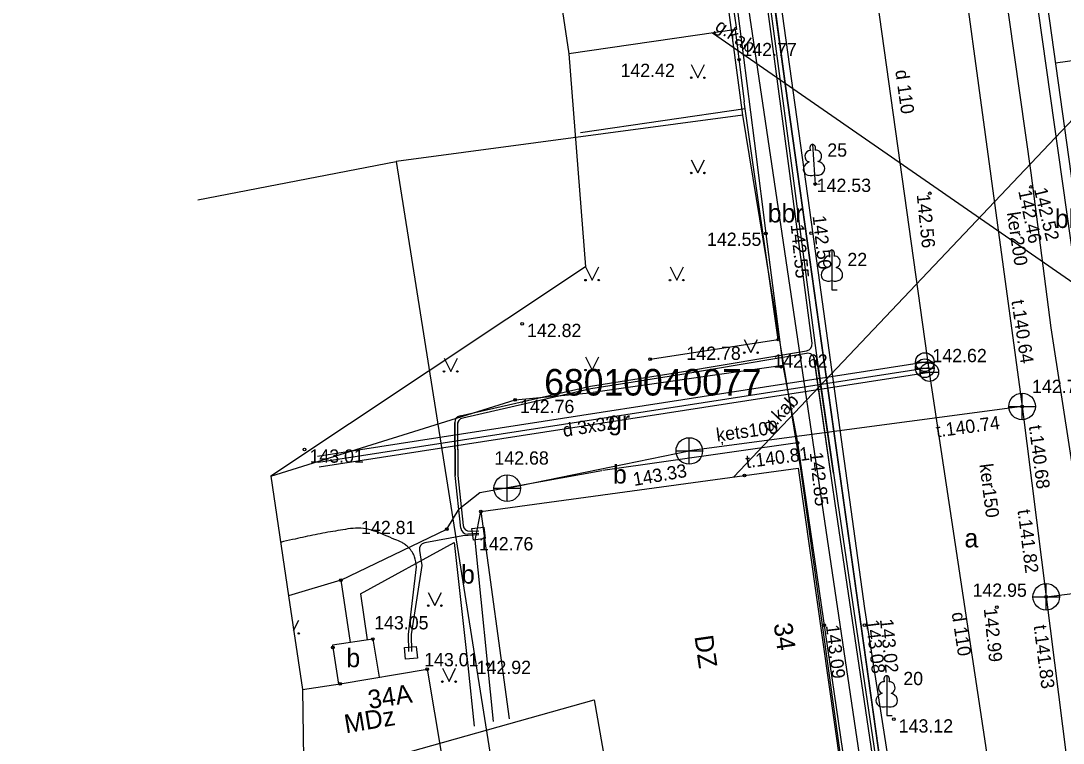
# Model space of a CAD drawing. Extents: x 728710 to 728960, y 272811 to 273475.
# Drawn here: x 728796 to 728835.24, y 273006.07 to 273033.26 of the extents above; entities that cross this region are included whole.
import ezdxf

# ---------------------------------------------------------------- set-up
doc = ezdxf.new("R2010")
doc.units = 0
for name, color, linetype in [('GEOD_ELEM_####_TKST_#', 7, 'Continuous'), ('Level 15', 7, 'Continuous'), ('Level 17', 7, 'Continuous'), ('Level 23', 7, 'Continuous'), ('Level 27', 7, 'Continuous'), ('Level 29', 7, 'Continuous'), ('Level 3', 7, 'Continuous'), ('Level 36', 7, 'Continuous'), ('Level 39', 7, 'Continuous'), ('Level 4', 7, 'Continuous'), ('Level 48', 7, 'Continuous'), ('Level 50', 7, 'Continuous'), ('Level 55', 7, 'Continuous'), ('Level 56', 7, 'Continuous'), ('Level 57', 7, 'Continuous'), ('Level 58', 7, 'Continuous'), ('Level 59', 7, 'Continuous'), ('Level 60', 7, 'Continuous'), ('Level 62', 7, 'Continuous'), ('Level 9', 7, 'Continuous'), ('PNTNO', 7, 'Continuous'), ('RAMI_UZMR_####_####_#', 7, 'Continuous'), ('RELJ_ELEM_####_####_#', 7, 'Continuous'), ('RELJ_NOGA_####_####_#', 7, 'Continuous'), ('ROBZ_ELEM_####_####_#', 7, 'Continuous'), ('ROBZ_KADS_####_TKST_#', 7, 'Continuous'), ('ROBZ_UZMR_####_####_#', 7, 'Continuous'), ('SAKT_VADV_PKAB_TKST_#', 7, 'Continuous'), ('TERT_ELEM_####_####_#', 7, 'Continuous'), ('TERT_KONT_####_####_#', 7, 'Continuous')]:
    doc.layers.add(name, color=color, linetype=linetype)

msp = doc.modelspace()

# ---------------------------------------------------------------- linework, layer by layer
at = {"layer": 'GEOD_ELEM_####_TKST_#'}
msp.add_lwpolyline([(728828.856, 273003.445), (728828.68, 273003.642), (728828.556, 273003.935), (728824.783, 273030.792), (728823.249, 273042.16), (728821.524, 273054.142), (728821.778, 273054.372)], dxfattribs=at)
at = {"layer": 'Level 15'}
for points in [[(728813.484, 273013.771), (728813.04, 273013.714), (728812.984, 273014.151), (728813.428, 273014.208)], [(728810.93, 273009.276), (728810.485, 273009.232), (728810.442, 273009.67), (728810.887, 273009.714)]]:
    msp.add_lwpolyline(points, close=True, dxfattribs=at)
at = {"layer": 'Level 17'}
for p, q in [((728807.174, 273016.87), (728830.144, 273020.432)), ((728807.209, 273016.644), (728830.179, 273020.207)), ((728807.236, 273016.472), (728830.206, 273020.034))]:
    msp.add_line(p, q, dxfattribs=at)
for points in [[(728826.802, 273044.347), (728830.203, 273020.034)], [(728830.203, 273020.034), (728832.551, 273004.399)]]:
    msp.add_lwpolyline(points, dxfattribs=at)
at = {"layer": 'Level 23'}
msp.add_line((728814.314, 273015.667), (728821.168, 273017.069), dxfattribs=at)
for points in [[(728826.189, 273073.896), (728833.694, 273018.747), (728821.168, 273017.069)], [(728833.694, 273018.747), (728834.604, 273011.578), (728842.609, 273012.599)], [(728834.604, 273011.578), (728838.604, 272979.894), (728842.796, 272980.305)]]:
    msp.add_lwpolyline(points, dxfattribs=at)
at = {"layer": 'Level 27'}
for points in [[(728822.896, 273032.936), (728823.238, 273030.207)], [(728819.695, 273020.523), (728824.516, 273021.259), (728823.238, 273030.207)], [(728823.275, 273029.949), (728817.067, 273029.042)]]:
    msp.add_lwpolyline(points, dxfattribs=at)
at = {"layer": 'Level 29'}
for p, q in [((728833.694, 273018.247), (728833.694, 273019.247)), ((728833.194, 273018.747), (728834.194, 273018.747)), ((728821.168, 273016.569), (728821.168, 273017.569)), ((728820.668, 273017.069), (728821.668, 273017.069)), ((728814.314, 273015.167), (728814.314, 273016.167)), ((728813.814, 273015.667), (728814.814, 273015.667)), ((728834.604, 273011.078), (728834.604, 273012.078)), ((728834.104, 273011.578), (728835.104, 273011.578))]:
    msp.add_line(p, q, dxfattribs=at)
for centre in [(728833.694, 273018.747), (728821.168, 273017.069), (728814.314, 273015.667), (728834.604, 273011.578)]:
    msp.add_circle(centre, 0.5, dxfattribs=at)
at = {"layer": 'Level 3'}
for p, q in [((728821.012, 273046.132), (728822.94, 273032.932)), ((728822.94, 273032.932), (728816.634, 273032.011)), ((728813.325, 273014.791), (728825.26, 273016.422)), ((728825.26, 273016.422), (728827.025, 273004.043)), ((728813.325, 273014.791), (728814.392, 273006.984)), ((728808.027, 273008.309), (728811.305, 273008.858)), ((728806.601, 273008.097), (728808.027, 273008.309))]:
    msp.add_line(p, q, dxfattribs=at)
msp.add_lwpolyline([(728811.305, 273008.858), (728812.119, 273004.001), (728808.786, 273003.415)], dxfattribs=at)
at = {"layer": 'Level 36'}
for p, q in [((728826.493, 273016.224), (728825.862, 273020.594)), ((728812.442, 273018.145), (728812.457, 273016.145))]:
    msp.add_line(p, q, dxfattribs=at)
for points in [[(728826.592, 273016.238), (728825.961, 273020.608)], [(728812.342, 273018.144), (728812.357, 273016.144)]]:
    msp.add_lwpolyline(points, dxfattribs=at)
at = {"layer": 'Level 39'}
for p, q in [((728829.682, 273020.414), (728830.384, 273020.414)), ((728830.032, 273020.414), (728830.032, 273020.415)), ((728829.681, 273020.184), (728830.383, 273020.184)), ((728829.852, 273020.034), (728830.554, 273020.034)), ((728830.031, 273020.184), (728830.031, 273020.185)), ((728830.202, 273020.034), (728830.202, 273020.035))]:
    msp.add_line(p, q, dxfattribs=at)
for centre in [(728830.033, 273020.414), (728830.032, 273020.184), (728830.203, 273020.034)]:
    msp.add_circle(centre, 0.351, dxfattribs=at)
at = {"layer": 'Level 4'}
for p, q in [((728820.196, 273055.436), (728823.604, 273028.739)), ((728834.947, 273031.673), (728843.115, 273032.795)), ((728823.604, 273028.739), (728824.1, 273024.852)), ((728824.1, 273024.852), (728824.683, 273020.291)), ((728824.683, 273020.291), (728817.545, 273019.273)), ((728825.242, 273017.378), (728817.914, 273016.333)), ((728825.242, 273017.378), (728827.666, 273000.729))]:
    msp.add_line(p, q, dxfattribs=at)
for points in [[(728845.654, 273100.85), (728832.719, 273098.413), (728826.071, 273097.316), (728825.017, 273097.001), (728824.765, 273096.832), (728824.532, 273096.455), (728824.532, 273096.455), (728826.161, 273084.877), (728827.437, 273076.575), (728829.749, 273059.3), (728831.728, 273043.761), (728834.021, 273027.538), (728834.782, 273021.709), (728836.279, 273011.943), (728839.357, 272993.501), (728839.499, 272992.383), (728841.21, 272978.381), (728843.301, 272966.86), (728843.797, 272965.94)], [(728845.919, 273099.374), (728832.98, 273096.936), (728826.409, 273095.852), (728826.143, 273095.772), (728827.647, 273085.083), (728828.941, 273076.709), (728831.314, 273059.418), (728833.202, 273044.226), (728835.526, 273027.512), (728836.266, 273021.924), (728837.76, 273012.18), (728840.331, 272994.327), (728840.331, 272994.327), (728840.331, 272994.327), (728842.687, 272979.229), (728844.615, 272968.066)], [(728791.727, 273091.506), (728811.654, 273095.023), (728814.654, 273095.178), (728815.22, 273095.032), (728815.785, 273094.657), (728816.384, 273093.154), (728816.384, 273093.154), (728817.477, 273084.163), (728819.263, 273073.354), (728821.261, 273057.957), (728825.757, 273025.679), (728827.763, 273011.141), (728832.943, 272977.993), (728834.913, 272963.328)], [(728824.683, 273020.291), (728825.242, 273017.378)], [(728814.609, 273018.994), (728817.545, 273019.273)], [(728805.412, 273016.121), (728814.609, 273018.994)], [(728812.039, 273014.124), (728812.509, 273014.896), (728813.281, 273015.51), (728817.878, 273016.34)], [(728813.801, 273006.889), (728813.108, 273013.716), (728813.325, 273014.791)], [(728808.054, 273012.208), (728812.039, 273014.124)], [(728808.788, 273011.694), (728812.319, 273013.625), (728812.828, 273008.991), (728813.069, 273006.707)], [(728808.054, 273012.208), (728806.079, 273011.62)], [(728808.054, 273012.208), (728808.402, 273009.866)], [(728808.788, 273011.694), (728809.045, 273009.961)]]:
    msp.add_lwpolyline(points, dxfattribs=at)
at = {"layer": 'Level 48'}
for centre in [(728823.039, 273031.795), (728825.9, 273027.115), (728834.029, 273027.004), (728830.224, 273026.767), (728824.049, 273025.255), (728825.757, 273025.265), (728814.874, 273021.856), (728824.516, 273021.259), (728819.695, 273020.523), (728819.695, 273020.523), (728824.621, 273020.24), (728814.609, 273018.994), (728833.694, 273018.747), (728806.685, 273017.128), (728825.242, 273017.378), (728823.242, 273016.15), (728813.325, 273014.791), (728812.039, 273014.124), (728808.054, 273012.208), (728834.605, 273011.581), (728832.748, 273011.189), (728826.248, 273010.515), (728827.763, 273010.515), (728807.752, 273009.677), (728809.258, 273009.993), (728811.305, 273008.858), (728813.582, 273009.049), (728808.027, 273008.309), (728828.868, 273006.976)]:
    msp.add_circle(centre, 0.05, dxfattribs=at)
at = {"layer": 'Level 9'}
for p, q in [((728809.258, 273009.993), (728807.739, 273009.767)), ((728807.739, 273009.767), (728807.957, 273008.299)), ((728809.258, 273009.993), (728809.499, 273008.555))]:
    msp.add_line(p, q, dxfattribs=at)
at = {"layer": 'RAMI_UZMR_####_####_#'}
for points in [[(728810.894, 273070.336), (728816.634, 273032.011), (728817.26, 273023.998), (728805.412, 273016.121), (728806.079, 273011.62), (728806.601, 273008.097), (728806.659, 273004.632), (728817.58, 273007.699), (728824.279, 272969.525), (728810.963, 272966.628), (728810.935, 272966.213), (728811.098, 272962.191), (728811.981, 272950.771), (728813.612, 272944.45), (728830.483, 272947.485), (728837.542, 272895.947)], [(728842.48, 273036.82), (728822.849, 273016.092)], [(728822.045, 273032.801), (728845.408, 273016.627)]]:
    msp.add_lwpolyline(points, dxfattribs=at)
at = {"layer": 'RELJ_ELEM_####_####_#'}
msp.add_lwpolyline([(728821.778, 273054.372), (728821.586, 273054.209), (728821.524, 273054.142), (728821.54, 273054.018), (728823.24, 273042.315), (728824.783, 273030.792), (728828.544, 273004.011), (728828.618, 273003.789), (728828.856, 273003.445)], dxfattribs=at)
at = {"layer": 'ROBZ_ELEM_####_####_#'}
msp.add_lwpolyline([(728815.186, 273091.969), (728820.435, 273053.684), (728833.431, 272966.054)], dxfattribs=at)
at = {"layer": 'ROBZ_UZMR_####_####_#'}
for p, q in [((728823.179, 273029.707), (728820.023, 273053.364)), ((728823.179, 273029.707), (728810.138, 273027.96)), ((728825.364, 273016.401), (728823.179, 273029.707)), ((728802.665, 273026.519), (728810.138, 273027.96)), ((728810.138, 273027.96), (728814.417, 273000.979)), ((728827.101, 273003.875), (728825.364, 273016.401))]:
    msp.add_line(p, q, dxfattribs=at)
at = {"layer": 'TERT_ELEM_####_####_#'}
for p, q in [((728812.919, 273014.046), (728813.24, 273014.067)), ((728812.645, 273013.878), (728811.208, 273013.612)), ((728813.25, 273013.918), (728812.645, 273013.878)), ((728813.247, 273013.967), (728812.83, 273013.94)), ((728811.007, 273013.327), (728811.098, 273012.758))]:
    msp.add_line(p, q, dxfattribs=at)
for points in [[(728815.267, 273094.223), (728815.717, 273091.871), (728816.832, 273085.52), (728817.881, 273078.643), (728818.508, 273074.355), (728819.658, 273066.192), (728820.712, 273058.74), (728821.479, 273053.332), (728822.695, 273044.505), (728823.883, 273036.26), (728825.025, 273027.716), (728825.927, 273020.849), (728826.755, 273015.106), (728828.259, 273004.946), (728828.26, 273004.941)], [(728825.79, 273021.122), (728824.925, 273027.702), (728823.783, 273036.246), (728822.595, 273044.491), (728821.414, 273053.07)], [(728832.465, 273047.568), (728833.163, 273041.758), (728834, 273035.77), (728836.422, 273018.61), (728837.731, 273009.628), (728838.803, 273002.448), (728839.303, 272998.864)], [(728812.537, 273018.39), (728817.448, 273019.51), (728820.868, 273020.046), (728825.584, 273020.843)], [(728825.582, 273020.742), (728820.884, 273019.948), (728817.466, 273019.412), (728812.637, 273018.31)], [(728828.161, 273004.927), (728828.161, 273004.932), (728826.657, 273015.092), (728825.871, 273020.531)], [(728812.565, 273014.164), (728812.357, 273016.144), (728812.342, 273018.144)], [(728812.443, 273018.064), (728812.457, 273016.15), (728812.654, 273014.27)], [(728810.615, 273009.523), (728810.594, 273010.167), (728810.897, 273012.707)], [(728811.098, 273012.758), (728810.694, 273010.163), (728810.714, 273009.526)]]:
    msp.add_lwpolyline(points, dxfattribs=at)
for centre, start, end in [((728825.542, 273021.09), 279.5905, 7.4831), ((728825.624, 273020.495), 8.2139, 99.5905), ((728812.592, 273018.146), 102.8541, 180.4248), ((728812.693, 273018.066), 102.8541, 180.4248), ((728812.813, 273014.19), 185.988, 273.7394), ((728812.903, 273014.296), 185.988, 273.7394), ((728811.254, 273013.367), 100.4731, 189.1179)]:
    msp.add_arc(centre, 0.25, start, end, dxfattribs=at)
msp.add_spline([(728810.897, 273012.707), (728810.824, 273013.086), (728810.599, 273013.435), (728810.481, 273013.542), (728810.357, 273013.622), (728810.086, 273013.741), (728809.693, 273013.905), (728809.3, 273014.055), (728808.906, 273014.151), (728808.508, 273014.157), (728808.129, 273014.103), (728807.75, 273014.041), (728806.99, 273013.898), (728806.232, 273013.735), (728805.781, 273013.63)], degree=3, dxfattribs=at)
at = {"layer": 'TERT_KONT_####_####_#'}
for p, q in [((728821.24, 273031.616), (728821.49, 273031.116)), ((728821.49, 273031.116), (728821.74, 273031.616)), ((728821.24, 273028.031), (728821.49, 273027.531)), ((728821.49, 273027.531), (728821.74, 273028.031)), ((728825.878, 273027.461), (728825.9, 273027.115)), ((728825.9, 273027.115), (728826.099, 273027.128)), ((728817.26, 273023.998), (728817.51, 273023.498)), ((728817.51, 273023.498), (728817.76, 273023.998)), ((728820.444, 273023.998), (728820.694, 273023.498)), ((728820.694, 273023.498), (728820.944, 273023.998)), ((728826.534, 273023.48), (728826.534, 273023.133)), ((728826.534, 273023.133), (728826.734, 273023.133)), ((728823.237, 273021.269), (728823.487, 273020.769)), ((728823.487, 273020.769), (728823.737, 273021.269)), ((728811.936, 273020.562), (728812.186, 273020.062)), ((728812.186, 273020.062), (728812.436, 273020.562)), ((728817.26, 273020.612), (728817.51, 273020.112)), ((728817.51, 273020.112), (728817.76, 273020.612)), ((728811.339, 273011.749), (728811.589, 273011.249)), ((728811.589, 273011.249), (728811.839, 273011.749)), ((728806.272, 273010.316), (728806.466, 273010.704)), ((728811.872, 273008.89), (728812.122, 273008.39)), ((728812.122, 273008.39), (728812.372, 273008.89)), ((728828.598, 273007.459), (728828.598, 273007.112)), ((728828.598, 273007.112), (728828.798, 273007.112))]:
    msp.add_line(p, q, dxfattribs=at)
for points in [[(728825.804, 273028.612), (728825.878, 273027.461)], [(728825.909, 273028.386), (728825.908, 273028.387)], [(728826.534, 273024.633), (728826.534, 273023.48)], [(728826.623, 273024.401), (728826.622, 273024.402)], [(728828.598, 273008.612), (728828.598, 273007.459)], [(728828.688, 273008.38), (728828.687, 273008.381)]]:
    msp.add_lwpolyline(points, dxfattribs=at)
for centre, radius in [((728821.239, 273031.116), 0.028), ((728821.739, 273031.116), 0.0263), ((728821.239, 273027.531), 0.028), ((728821.739, 273027.531), 0.0263), ((728817.259, 273023.498), 0.028), ((728817.759, 273023.498), 0.0263), ((728820.443, 273023.498), 0.028), ((728820.943, 273023.498), 0.0263), ((728823.237, 273020.768), 0.028), ((728823.737, 273020.768), 0.0263), ((728811.936, 273020.062), 0.028), ((728812.436, 273020.062), 0.0263), ((728817.259, 273020.112), 0.028), ((728817.759, 273020.112), 0.0263), ((728811.339, 273011.249), 0.028), ((728811.839, 273011.249), 0.0263), ((728806.466, 273010.203), 0.0263), ((728811.872, 273008.389), 0.028), ((728812.372, 273008.389), 0.0263)]:
    msp.add_circle(centre, radius, dxfattribs=at)
for centre, major_axis, ratio, start_param, end_param in [((728825.814, 273028.463), (0.01, -0.15), 0.707107, 3.14537, 5.287485), ((728825.814, 273028.462), (0.01, -0.15), 0.707107, 0.995701, 3.137816), ((728825.705, 273028.16), (-0.025, -0.214), 0.861323, 3.141593, 6.283185), ((728825.961, 273028.176), (0.052, -0.21), 0.861323, 0, 3.141593), ((728825.773, 273027.701), (0.3, 0.114), 0.814445, 1.570796, 4.752015), ((728825.951, 273027.713), (-0.312, 0.075), 0.814445, 1.531171, 4.712389), ((728826.534, 273024.484), (0, -0.15), 0.707107, 3.14537, 5.287485), ((728826.533, 273024.484), (0, -0.15), 0.707107, 0.995701, 3.137816), ((728826.405, 273024.189), (-0.039, -0.212), 0.861323, 3.141593, 6.283185), ((728826.662, 273024.189), (0.039, -0.212), 0.861323, 0, 3.141593), ((728826.444, 273023.726), (0.307, 0.095), 0.814445, 1.570796, 4.752015), ((728826.623, 273023.726), (-0.307, 0.095), 0.814445, 1.531171, 4.712389), ((728828.598, 273008.462), (0, -0.15), 0.707107, 3.14537, 5.287485), ((728828.598, 273008.462), (0, -0.15), 0.707107, 0.995701, 3.137816), ((728828.47, 273008.167), (-0.039, -0.212), 0.861323, 3.141593, 6.283185), ((728828.726, 273008.167), (0.039, -0.212), 0.861323, 0, 3.141593), ((728828.508, 273007.705), (0.307, 0.095), 0.814445, 1.570796, 4.752015), ((728828.688, 273007.705), (-0.307, 0.095), 0.814445, 1.531171, 4.712389)]:
    msp.add_ellipse(centre, major_axis=major_axis, ratio=ratio, start_param=start_param, end_param=end_param, dxfattribs=at)

# ---------------------------------------------------------------- texts
at = {"layer": 'Level 50'}
msp.add_text('b', height=0.7, dxfattribs=at).set_placement((728808.258, 273008.933))
at = {"layer": 'Level 55'}
for s, rotation, p in [('d 110', 277.9631, (728828.919, 273031.381)), ('d 3x32', 8.8167, (728816.444, 273017.596)), ('d 110', 278.542, (728831.042, 273010.974))]:
    msp.add_text(s, height=0.5, rotation=rotation, dxfattribs=at).set_placement(p)
at = {"layer": 'Level 56'}
for s, p in [(' 142.70', (728833.883, 273019.247)), (' 142.68', (728813.647, 273016.555)), (' 142.95', (728831.644, 273011.581))]:
    msp.add_text(s, height=0.5, dxfattribs=at).set_placement(p)
at = {"layer": 'Level 57'}
for s, p in [(' 142.77', (728822.981, 273031.927)), (' 142.42', (728818.392, 273031.143)), (' 142.53', (728825.779, 273026.817)), ('142.55', (728821.834, 273024.787)), (' 142.82', (728814.874, 273021.356)), (' 142.78', (728820.874, 273020.497)), (' 142.62', (728824.145, 273020.206)), (' 142.76', (728814.609, 273018.494)), (' 143.01', (728806.685, 273016.628)), (' 142.81', (728808.627, 273013.94)), (' 142.76', (728813.065, 273013.328)), (' 143.05', (728809.119, 273010.355)), (' 143.01', (728811.001, 273008.965)), (' 142.92', (728812.978, 273008.676)), (' 143.12', (728828.866, 273006.473))]:
    msp.add_text(s, height=0.5, dxfattribs=at).set_placement(p)
for s, rotation, p in [('142.52', 283.5724, (728834.136, 273026.92)), ('142.56', 275.772, (728829.727, 273026.717)), ('142.46', 281.5255, (728833.549, 273026.848)), ('142.50', 276.285, (728825.808, 273025.912)), ('142.55', 275.6677, (728824.983, 273025.581)), (' 142.85', 275.9568, (728825.68, 273017.19)), (' 143.33', 9.8364, (728818.909, 273015.718)), ('142.99', 275.8704, (728832.251, 273011.138)), ('143.09', 276.8543, (728826.306, 273010.506)), ('143.08', 276.8543, (728827.808, 273010.696)), ('143.02', 275.8917, (728828.342, 273010.727))]:
    msp.add_text(s, height=0.5, rotation=rotation, dxfattribs=at).set_placement(p)
at = {"layer": 'Level 58'}
for s, p in [('bbr', (728824.12, 273025.668)), ('bbr', (728834.929, 273025.461)), ('gr', (728818.111, 273017.863)), ('b', (728818.295, 273015.844)), ('a', (728831.525, 273013.44)), ('b', (728812.573, 273012.077))]:
    msp.add_text(s, height=0.7, dxfattribs=at).set_placement(p)
at = {"layer": 'Level 59'}
for s, rotation, p in [('DZ', 278.115, (728821.36, 273010.092)), ('MDz', 9.5077, (728808.24, 273006.443))]:
    msp.add_text(s, height=0.7, rotation=rotation, dxfattribs=at).set_placement(p)
at = {"layer": 'Level 60'}
for s, rotation, p in [('ker200', 278.445, (728833.118, 273026.033)), ('t.140.64', 278.445, (728833.29, 273022.72)), ('t.140.74', 7.628, (728830.486, 273017.579)), ('ķets100', 7.628, (728822.215, 273017.421)), ('t.140.68', 277.234, (728833.949, 273018.01)), ('t.140.81', 7.628, (728823.321, 273016.42)), ('ker150', 277.234, (728832.088, 273016.561)), ('t.141.82', 277.195, (728833.522, 273014.84)), ('t.141.83', 277.195, (728834.128, 273010.492))]:
    msp.add_text(s, height=0.5, rotation=rotation, dxfattribs=at).set_placement(p)
at = {"layer": 'Level 62'}
for s, rotation, p in [('34', 278.115, (728824.339, 273010.557)), ('34A', 8.6436, (728809.124, 273007.358))]:
    msp.add_text(s, height=0.7, rotation=rotation, dxfattribs=at).set_placement(p)
at = {"layer": 'PNTNO'}
msp.add_text(' 142.62', height=0.5, dxfattribs=at).set_placement((728830.135, 273020.411))
at = {"layer": 'RELJ_NOGA_####_####_#'}
for s, p in [('25', (728826.363, 273028.145)), ('22', (728827.119, 273024.025)), ('20', (728829.224, 273008.257))]:
    msp.add_text(s, height=0.5, dxfattribs=at).set_placement(p)
at = {"layer": 'ROBZ_KADS_####_TKST_#'}
msp.add_text('68010040077', height=1, dxfattribs=at).set_placement((728815.706, 273019.155))
at = {"layer": 'SAKT_VADV_PKAB_TKST_#'}
for rotation, p in [(325.3043, (728822.095, 273032.949)), (46.5552, (728824.203, 273017.741))]:
    msp.add_text('g.kab', height=0.5, rotation=rotation, dxfattribs=at).set_placement(p)

doc.saveas('drawing.dxf')
